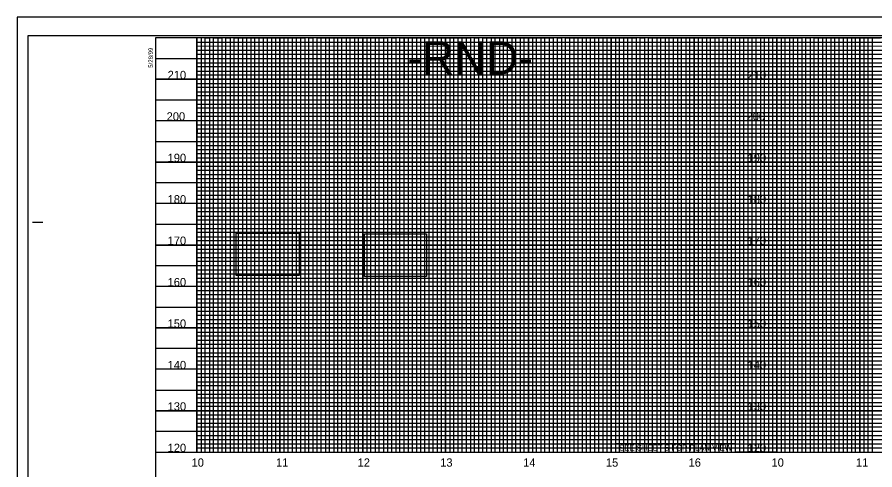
# Model space of a CAD drawing. Extents: x 1779926 to 1781626, y 618464 to 619564.
# Drawn here: x 1779926 to 1780961, y 619018 to 619564 of the extents above; entities that cross this region are included whole.
import ezdxf

# ---------------------------------------------------------------- set-up
doc = ezdxf.new("R2010")
doc.units = 0
for name, color, linetype in [('Exist Vertical Profile Horizontal Axis Label Major', 7, 'Continuous'), ('Exist Vertical Profile Vertical Axis Label', 7, 'Continuous'), ('Prop DSN Text', 7, 'Continuous'), ('Prop Grid Mask', 7, 'Continuous'), ('Sheet DOT Grid CELL', 7, 'Continuous'), ('Sheet Layout Profile Border Port 1', 7, 'Continuous'), ('Sheet Plot Border Inside CELL', 7, 'Continuous'), ('Sheet Plot Border Outside CELL', 7, 'Continuous'), ('Sheet Profile CELL', 7, 'Continuous'), ('Sheet Profile Grid Major CELL', 7, 'Continuous'), ('Sheet Profile Grid Middle CELL', 7, 'Continuous'), ('Sheet Profile Grid Minor CELL', 7, 'Continuous')]:
    doc.layers.add(name, color=color, linetype=linetype)

msp = doc.modelspace()

# ---------------------------------------------------------------- linework, layer by layer
at = {"layer": 'Prop Grid Mask'}
for points in [[(1780562.8, 619539.2), (1780393.1, 619539.2), (1780393.1, 619489.2), (1780562.8, 619489.2)], [(1780793, 619539.2), (1780843, 619539.2), (1780843, 619039.2), (1780793, 619039.2)], [(1780190.3, 619303.4), (1780266.2, 619303.4), (1780266.2, 619252.4), (1780190.3, 619252.4)], [(1780345.3, 619302.5), (1780420.1, 619302.5), (1780420.1, 619251.4), (1780345.3, 619251.4)], [(1780793, 619049.2), (1780648, 619049.2), (1780648, 619039.2), (1780793, 619039.2)]]:
    msp.add_lwpolyline(points, close=True, dxfattribs=at)
at = {"layer": 'Sheet DOT Grid CELL'}
for p, q in [((1780143, 619039.2), (1780143, 619539.2)), ((1780193, 619039.2), (1780193, 619539.2)), ((1780243, 619039.2), (1780243, 619539.2)), ((1780293, 619039.2), (1780293, 619539.2)), ((1780343, 619039.2), (1780343, 619539.2)), ((1780393, 619039.2), (1780393, 619539.2)), ((1780443, 619039.2), (1780443, 619539.2)), ((1780493, 619039.2), (1780493, 619539.2)), ((1780543, 619039.2), (1780543, 619539.2)), ((1780593, 619039.2), (1780593, 619539.2)), ((1780643, 619039.2), (1780643, 619539.2)), ((1780693, 619039.2), (1780693, 619539.2)), ((1780743, 619039.2), (1780743, 619539.2)), ((1780793, 619039.2), (1780793, 619539.2)), ((1780843, 619039.2), (1780843, 619539.2)), ((1780893, 619039.2), (1780893, 619539.2)), ((1780943, 619039.2), (1780943, 619539.2)), ((1781392.9, 619489.2), (1780093, 619489.2)), ((1781392.9, 619439.2), (1780093, 619439.2)), ((1781393, 619389.2), (1780093, 619389.2)), ((1781392.9, 619339.2), (1780093, 619339.2)), ((1781593, 619289.2), (1780093, 619289.2)), ((1781593, 619239.2), (1780093, 619239.2)), ((1781593, 619189.2), (1780093, 619189.2)), ((1781593, 619139.2), (1780093, 619139.2)), ((1781593, 619089.2), (1780093, 619089.2))]:
    msp.add_line(p, q, dxfattribs=at)
at = {"layer": 'Sheet Layout Profile Border Port 1'}
for points in [[(1781543, 619099.2), (1781543, 619314.2), (1781392.9, 619314.2), (1781393, 619539.2), (1780143, 619539.2), (1780143, 619039.2), (1781543, 619039.2), (1781543, 619049.2)], [(1780143, 619378.1), (1780143, 619039.2), (1781543, 619039.2), (1781543, 619314.2)]]:
    msp.add_lwpolyline(points, dxfattribs=at)
at = {"layer": 'Sheet Plot Border Inside CELL'}
msp.add_lwpolyline([(1779939, 618486.6), (1781605.5, 618486.6), (1781605.5, 619541.7), (1779939, 619541.7)], close=True, dxfattribs=at)
at = {"layer": 'Sheet Plot Border Outside CELL'}
msp.add_lwpolyline([(1779926, 618464.2), (1781626, 618464.2), (1781626, 619564.2), (1779926, 619564.2)], close=True, dxfattribs=at)
at = {"layer": 'Sheet Profile CELL'}
for p, q in [((1779944.5, 619316.7), (1779957, 619316.7)), ((1780093, 619039.2), (1781593, 619039.2))]:
    msp.add_line(p, q, dxfattribs=at)
msp.add_lwpolyline([(1781593, 619539.2), (1780093, 619539.2), (1780093, 618489.2), (1781593, 618489.2)], close=True, dxfattribs=at)
at = {"layer": 'Sheet Profile Grid Major CELL'}
for points in [[(1780143, 619539.2), (1780143, 619039.2), (1780193, 619039.2), (1780193, 619539.2), (1780243, 619539.2), (1780243, 619039.2), (1780293, 619039.2), (1780293, 619539.2), (1780343, 619539.2), (1780343, 619039.2), (1780393, 619039.2), (1780393, 619539.2), (1780443, 619539.2), (1780443, 619039.2), (1780493, 619039.2), (1780493, 619539.2), (1780543, 619539.2), (1780543, 619039.2), (1780593, 619039.2), (1780593, 619539.2), (1780643, 619539.2), (1780643, 619039.2), (1780693, 619039.2), (1780693, 619539.2), (1780743, 619539.2), (1780743, 619039.2), (1780793, 619039.2), (1780793, 619539.2), (1780843, 619539.2), (1780843, 619039.2), (1780893, 619039.2), (1780893, 619539.2), (1780943, 619539.2), (1780943, 619039.2), (1780993, 619039.2)], [(1780093, 619489.2), (1781393, 619489.2)], [(1781393, 619439.2), (1780093, 619439.2), (1780093, 619389.2), (1781393, 619389.2)], [(1781393, 619339.2), (1780093, 619339.2), (1780093, 619289.2), (1781593, 619289.2)], [(1781593, 619239.2), (1780093, 619239.2), (1780093, 619189.2), (1781593, 619189.2)], [(1781593, 619139.2), (1780093, 619139.2), (1780093, 619139.2), (1780093, 619089.2), (1781593, 619089.2)]]:
    msp.add_lwpolyline(points, dxfattribs=at)
at = {"layer": 'Sheet Profile Grid Middle CELL'}
msp.add_line((1780093, 619514.2), (1781392.9, 619514.2), dxfattribs=at)
for points in [[(1780168, 619539.2), (1780168, 619039.2), (1780218, 619039.2), (1780218, 619539.2), (1780268, 619539.2), (1780268, 619039.2), (1780318, 619039.2), (1780318, 619539.2), (1780368, 619539.2), (1780368, 619039.2), (1780418, 619039.2), (1780418, 619539.2), (1780468, 619539.2), (1780468, 619039.2), (1780518, 619039.2), (1780518, 619539.2), (1780568, 619539.2), (1780568, 619039.2), (1780618, 619039.2), (1780618, 619539.2), (1780668, 619539.2), (1780668, 619039.2), (1780718, 619039.2), (1780718, 619039.2), (1780718, 619539.2), (1780768, 619539.2), (1780768, 619039.2), (1780818, 619039.2), (1780818, 619539.2), (1780868, 619539.2), (1780868, 619039.2), (1780918, 619039.2), (1780918, 619539.2), (1780968, 619539.2)], [(1781393, 619464.2), (1780093, 619464.2), (1780093, 619414.2), (1781393, 619414.2)], [(1781392.9, 619364.2), (1780093, 619364.2), (1780093, 619314.2), (1781418, 619314.2)], [(1781593, 619264.2), (1780093, 619264.2), (1780093, 619214.2), (1781593, 619214.2)], [(1781593, 619164.2), (1780093, 619164.2), (1780093, 619114.2), (1781593, 619114.2)], [(1781593, 619064.2), (1780093, 619064.2)]]:
    msp.add_lwpolyline(points, dxfattribs=at)
at = {"layer": 'Sheet Profile Grid Minor CELL'}
for p, q in [((1780143, 619534.2), (1781393, 619534.2)), ((1780143, 619529.2), (1780143, 619529.2)), ((1781393, 619529.2), (1780143, 619528.8)), ((1780143, 619524.2), (1781393, 619524.2)), ((1781392.9, 619404.2), (1780143, 619404.2)), ((1781393, 619399.2), (1780143, 619399.2)), ((1781393, 619394.2), (1780143, 619394.2)), ((1780143, 619384.2), (1781393, 619384.2)), ((1781393, 619379.2), (1780143, 619379.2)), ((1780143, 619374.2), (1781392.9, 619374.2)), ((1781392.9, 619354.2), (1780143, 619354.2)), ((1780143, 619349.2), (1781392.9, 619349.2)), ((1781392.9, 619329.2), (1780143, 619329.2)), ((1780143, 619324.2), (1781392.9, 619324.2)), ((1781543, 619304.2), (1780143, 619304.2)), ((1780143, 619299.2), (1781543, 619299.2)), ((1781543, 619294.2), (1780143, 619294.2)), ((1780143, 619284.2), (1781543, 619284.2)), ((1781543, 619279.2), (1780143, 619279.2)), ((1780143, 619274.2), (1781543, 619274.2)), ((1781543, 619269.2), (1780143, 619269.2)), ((1780143, 619259.2), (1781543, 619259.2)), ((1781543, 619254.2), (1780143, 619254.2)), ((1780143, 619249.2), (1781543, 619249.2)), ((1781543, 619244.2), (1780143, 619244.2)), ((1780143, 619234.2), (1781543, 619234.2)), ((1781543, 619229.2), (1780143, 619229.2)), ((1780143, 619224.2), (1781543, 619224.2)), ((1781543, 619219.2), (1780143, 619219.2)), ((1780143, 619209.2), (1781543, 619209.2)), ((1781543, 619204.2), (1780143, 619204.2)), ((1780143, 619199.2), (1781543, 619199.2)), ((1781543, 619194.2), (1780143, 619194.2)), ((1780143, 619184.2), (1781543, 619184.2)), ((1781543, 619179.2), (1780143, 619179.2)), ((1780143, 619174.2), (1781543, 619174.2)), ((1781543, 619169.2), (1780143, 619169.2)), ((1780143, 619159.2), (1781543, 619159.2)), ((1781543, 619154.2), (1780143, 619154.2)), ((1781543, 619149.2), (1780143, 619149.2)), ((1781543, 619144.2), (1780143, 619144.2)), ((1780143, 619134.2), (1781543, 619134.2)), ((1781543, 619129.2), (1780143, 619129.2)), ((1780143, 619124.2), (1781543, 619124.2)), ((1781543, 619119.2), (1780143, 619119.2)), ((1780143, 619109.2), (1781543, 619109.2)), ((1781543, 619104.2), (1780143, 619104.2)), ((1780143, 619099.2), (1781543, 619099.2)), ((1781543, 619094.2), (1780143, 619094.2)), ((1780143, 619084.2), (1781543, 619084.2)), ((1781543, 619079.2), (1780143, 619079.2)), ((1780143, 619074.2), (1781543, 619074.2)), ((1781543, 619069.2), (1780143, 619069.2)), ((1780143, 619059.2), (1781543, 619059.2)), ((1781543, 619054.2), (1780143, 619054.2)), ((1780143, 619049.2), (1781543, 619049.2))]:
    msp.add_line(p, q, dxfattribs=at)
for points in [[(1780148, 619539.2), (1780148, 619039.2), (1780153, 619039.2), (1780153, 619539.2), (1780158, 619539.2), (1780158, 619039.2), (1780163, 619039.2), (1780163, 619539.2), (1780173, 619539.2), (1780173, 619039.2), (1780178, 619039.2), (1780178, 619539.2), (1780183, 619539.2), (1780183, 619039.2), (1780188, 619039.2), (1780198, 619039.2), (1780203, 619039.2), (1780203, 619539.2), (1780208, 619539.2), (1780208, 619039.2), (1780213, 619039.2), (1780213, 619539.2), (1780223, 619539.2), (1780223, 619039.2), (1780228, 619039.2), (1780228, 619539.2), (1780233, 619539.2), (1780233, 619039.2), (1780238, 619039.2), (1780238, 619539.2), (1780248, 619539.2), (1780248, 619039.2), (1780253, 619039.2), (1780253, 619539.2), (1780258, 619539.2), (1780258, 619039.2), (1780263, 619039.2), (1780263, 619539.2), (1780273, 619539.2), (1780273, 619039.2), (1780278, 619039.2), (1780278, 619539.2), (1780283, 619539.2), (1780283, 619039.2), (1780288, 619039.2), (1780288, 619539.2), (1780298, 619539.2), (1780298, 619039.2), (1780303, 619039.2), (1780303, 619539.2), (1780308, 619539.2), (1780308, 619039.2), (1780313, 619039.2), (1780313, 619539.2), (1780323, 619539.2), (1780323, 619039.2), (1780328, 619039.2), (1780328, 619539.2), (1780333, 619539.2), (1780333, 619039.2), (1780338, 619039.2), (1780338, 619539.2), (1780348, 619539.2), (1780348, 619039.2), (1780353, 619039.2), (1780353, 619539.2), (1780358, 619539.2), (1780358, 619039.2)], [(1780188, 619039.2), (1780188, 619539.2), (1780198, 619539.2), (1780198, 619039.2)], [(1780358, 619039.2), (1780363, 619039.2), (1780363, 619539.2), (1780373, 619539.2), (1780373, 619039.2), (1780378, 619039.2), (1780378, 619539.2), (1780383, 619539.2), (1780383, 619039.2), (1780388, 619039.2), (1780388, 619539.2), (1780398, 619539.2), (1780398, 619039.2), (1780403, 619039.2), (1780403, 619539.2), (1780408, 619539.2), (1780408, 619039.2), (1780413, 619039.2), (1780413, 619539.2), (1780423, 619539.2), (1780423, 619039.2), (1780428, 619039.2), (1780428, 619539.2), (1780433, 619539.2), (1780433, 619039.2), (1780438, 619039.2), (1780438, 619539.2), (1780448, 619539.2), (1780448, 619039.2), (1780453, 619039.2), (1780453, 619539.2), (1780458, 619539.2), (1780458, 619039.2), (1780463, 619039.2), (1780463, 619539.2), (1780473, 619539.2), (1780473, 619039.2), (1780478, 619039.2), (1780478, 619539.2), (1780483, 619539.2), (1780483, 619039.2), (1780488, 619039.2), (1780488, 619539.2), (1780498, 619539.2), (1780498, 619039.2), (1780503, 619039.2), (1780503, 619539.2), (1780508, 619539.2), (1780508, 619039.2), (1780513, 619039.2), (1780513, 619539.2), (1780523, 619539.2), (1780523, 619039.2), (1780528, 619039.2), (1780528, 619539.2), (1780533, 619539.2), (1780533, 619039.2), (1780538, 619039.2), (1780538, 619539.2), (1780548, 619539.2), (1780548, 619039.2), (1780553, 619039.2), (1780553, 619539.2), (1780558, 619539.2), (1780558, 619039.2), (1780563, 619039.2), (1780563, 619539.2), (1780573, 619539.2), (1780573, 619039.2), (1780578, 619039.2), (1780578, 619539.2), (1780583, 619539.2), (1780583, 619039.2), (1780588, 619039.2), (1780588, 619539.2), (1780598, 619539.2), (1780598, 619039.2), (1780603, 619039.2), (1780603, 619539.2), (1780608, 619539.2), (1780608, 619039.2), (1780613, 619039.2), (1780613, 619539.2), (1780623, 619539.2), (1780623, 619039.2), (1780628, 619039.2), (1780628, 619539.2), (1780633, 619539.2), (1780633, 619039.2), (1780638, 619039.2), (1780638, 619539.2), (1780648, 619539.2), (1780648, 619039.2), (1780653, 619039.2), (1780653, 619539.2), (1780658, 619539.2), (1780658, 619039.2), (1780663, 619039.2), (1780663, 619539.2), (1780673, 619539.2)], [(1780673, 619539.2), (1780673, 619039.2), (1780678, 619039.2), (1780678, 619539.2), (1780683, 619539.2), (1780683, 619039.2), (1780688, 619039.2), (1780688, 619539.2), (1780698, 619539.2), (1780698, 619039.2), (1780703, 619039.2), (1780703, 619539.2), (1780708, 619539.2), (1780708, 619039.2), (1780713, 619039.2), (1780713, 619539.2), (1780723, 619539.2), (1780723, 619039.2), (1780728, 619039.2), (1780728, 619539.2), (1780733, 619539.2), (1780733, 619039.2), (1780738, 619039.2), (1780738, 619539.2), (1780748, 619539.2), (1780748, 619039.2), (1780753, 619039.2), (1780753, 619539.2), (1780758, 619539.2), (1780758, 619039.2), (1780763, 619039.2), (1780763, 619539.2), (1780773, 619539.2), (1780773, 619039.2), (1780778, 619039.2), (1780778, 619539.2), (1780783, 619539.2), (1780783, 619039.2), (1780788, 619039.2), (1780788, 619539.2), (1780798, 619539.2), (1780798, 619039.2), (1780798, 619039.2), (1780803, 619039.2), (1780803, 619539.2), (1780808, 619539.2), (1780808, 619039.2), (1780813, 619039.2), (1780813, 619539.2), (1780823, 619539.2), (1780823, 619039.2), (1780828, 619039.2), (1780828, 619539.2), (1780833, 619539.2), (1780833, 619039.2), (1780838, 619039.2), (1780838, 619539.2), (1780848, 619539.2), (1780848, 619039.2), (1780853, 619039.2), (1780853, 619539.2), (1780858, 619539.2), (1780858, 619039.2), (1780863, 619039.2), (1780863, 619539.2), (1780873, 619539.2), (1780873, 619039.2), (1780878, 619039.2), (1780878, 619539.2), (1780883, 619539.2), (1780883, 619039.2), (1780888, 619039.2), (1780888, 619539.2), (1780898, 619539.2), (1780898, 619039.2), (1780903, 619039.2), (1780903, 619539.2), (1780908, 619539.2), (1780908, 619039.2), (1780913, 619039.2), (1780913, 619539.2), (1780923, 619539.2), (1780923, 619039.2), (1780928, 619039.2), (1780928, 619539.2), (1780933, 619539.2), (1780933, 619039.2), (1780938, 619039.2), (1780938, 619539.2), (1780948, 619539.2), (1780948, 619039.2), (1780952.7, 619039.7), (1780953, 619039.2), (1780953, 619539.2), (1780958, 619539.2), (1780958, 619039.2), (1780963, 619039.2)], [(1781393, 619519.2), (1780143, 619519.2), (1780143, 619509.2), (1781393, 619509.2)], [(1781392.9, 619504.2), (1780143, 619504.2), (1780143, 619499.2), (1781393, 619499.2)], [(1781393, 619494.2), (1780143, 619494.2), (1780143, 619484.2), (1781393, 619484.2)], [(1781393, 619479.2), (1780143, 619479.2), (1780143, 619474.2), (1781393, 619474.2)], [(1781393, 619469.2), (1780143, 619469.2), (1780143, 619459.2), (1781393, 619459.2)], [(1781393, 619454.2), (1780143, 619454.2), (1780143, 619449.2), (1781393, 619449.2)], [(1781393, 619444.2), (1780143, 619444.2), (1780143, 619434.2), (1781393, 619434.2)], [(1781393, 619429.1), (1780143.1, 619429.1), (1780143.1, 619424.2), (1781393, 619424.2)], [(1781393, 619419.2), (1780143, 619419.2), (1780143, 619409.2), (1781393, 619409.2)], [(1781392.9, 619369.2), (1780143, 619369.2), (1780143, 619359.2), (1781392.9, 619359.2)], [(1781392.9, 619344.2), (1780143, 619344.2), (1780143, 619334.2), (1781392.9, 619334.2)], [(1781392.9, 619319.2), (1780143, 619319.2), (1780143, 619309.2), (1781543, 619309.2)], [(1781543, 619044.2), (1780143, 619044.2)]]:
    msp.add_lwpolyline(points, dxfattribs=at)

# ---------------------------------------------------------------- texts
at = {"layer": 'Exist Vertical Profile Horizontal Axis Label Major'}
for s, p in [('10', (1780136.5, 619021.7)), ('11', (1780238.4, 619021.7)), ('12', (1780336.9, 619021.7)), ('13', (1780436.6, 619021.7)), ('14', (1780536.7, 619021.7)), ('15', (1780636.6, 619021.7)), ('16', (1780736.4, 619021.7)), ('10', (1780836.5, 619021.7)), ('11', (1780938.4, 619021.7))]:
    msp.add_text(s, height=10, dxfattribs=at).set_placement(p)
at = {"layer": 'Exist Vertical Profile Vertical Axis Label'}
for s, p in [('210', (1780107.6, 619489.4)), ('210', (1780807.6, 619489.4)), ('200', (1780106.4, 619439.4)), ('200', (1780806.4, 619439.4)), ('190', (1780107.6, 619389.4)), ('190', (1780807.6, 619389.4)), ('180', (1780107.6, 619339.4)), ('180', (1780807.6, 619339.4)), ('170', (1780107.6, 619289.4)), ('170', (1780807.6, 619289.4)), ('160', (1780107.6, 619239.4)), ('160', (1780807.6, 619239.4)), ('150', (1780107.6, 619189.4)), ('150', (1780807.6, 619189.4)), ('140', (1780107.6, 619139.4)), ('140', (1780807.6, 619139.4)), ('130', (1780107.6, 619089.4)), ('130', (1780807.6, 619089.4)), ('120', (1780107.6, 619039.4)), ('120', (1780807.6, 619039.4))]:
    msp.add_text(s, height=10, dxfattribs=at).set_placement(p)
at = {"layer": 'Prop DSN Text'}
for s, height, p in [('-RND-', 40, (1780397, 619495.1)), ('SEE SHEET 5 FOR PLAN VIEW', 7, (1780652.5, 619041.1))]:
    msp.add_text(s, height=height, dxfattribs=at).set_placement(p)
at = {"layer": 'Sheet Profile CELL'}
msp.add_text('5/28/99', height=5.25, rotation=90, dxfattribs=at).set_placement((1780089.7, 619503.1))

doc.saveas('drawing.dxf')
